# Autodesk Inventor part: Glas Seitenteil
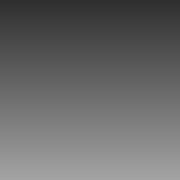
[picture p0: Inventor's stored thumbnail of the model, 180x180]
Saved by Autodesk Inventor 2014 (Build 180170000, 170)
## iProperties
Created: 2013-09
Part Number: Glas Seitenteil
Material: Glas
Document SubType Name: Modeling
Designer: Stefan Tammegger
Mass: 7853.77 g
Surface Area: 14714.3 cm^2
Volume: 3602.65 cm^3
Density: 2.18 g/cm^3
Appearance: Klar
Author: Stefan Tammegger
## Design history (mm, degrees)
workplane "Arbeitsebene1"
sketch "Skizze1"
  geometry: L1 (-356.465, 2780)-(-113.246, 0) reference; L2 (-114.996, 20)-(-5, 20) reference; L3 (-5, 0)-(-5, 2780) reference; L4 (-5, 2761.5)-(-354.846, 2761.5) reference; L5 (-371.216, 2776.5)-(10, 2776.5); L6 (10, 2776.5)-(10, 5); L7 (10, 5)-(-128.741, 5); L8 (-128.741, 5)-(-371.216, 2776.5); 1 further point
  constraints: 8 end point, 3 parallel, 1 perpendicular
  dimensions: "d0" = 15 distance between parallel lines of L1 L8; "d1" = 15 distance between parallel lines of L4 L5; "d2" = 15 distance between parallel lines of L6 L3; "d3" = 15 distance between parallel lines of L2 L7
extrude "Extrusion1" new body sketch "Skizze1" stored distance "d4" = 5; taper "d5" = 0 deg
node "Volumenkörper1"
node "Referenz1"
node "Referenz2"
node "Referenz3"
node "Referenz4"
